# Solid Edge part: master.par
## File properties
Author: Vicky Raina
Template: Normal.par
Last saved by: Robert a Rhodes jr
Revision: 1
Application: Solid Edge
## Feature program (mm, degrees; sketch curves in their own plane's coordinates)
body "unnamed Body 1"
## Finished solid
Body 1: solid body, 75 faces, 214 edges, 140 vertices.
  Faces by surface: cylinder 56, plane 19
  Edges by curve: circle 102, line 100, spline 12
Bounding box of the edges (mm): 7327.900 x 1778.000 x 2844.800, from (-1244.6, -355.6, -1422.4) to (6083.3, 1422.4, 1422.4).
Cylindrical faces by radius (mm): R152.4 x20, R304.8 x2, R330.2 x8, R444.5 x2, R635 x2, R660.4 x2, R800.1 x6, R1473.2 x4, R1828.8 x6, R1981.2 x4
Planar faces by outward normal: +y 5, +z 2, -x 1, -y 5, -z 2, oblique 4
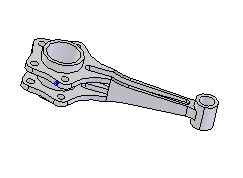
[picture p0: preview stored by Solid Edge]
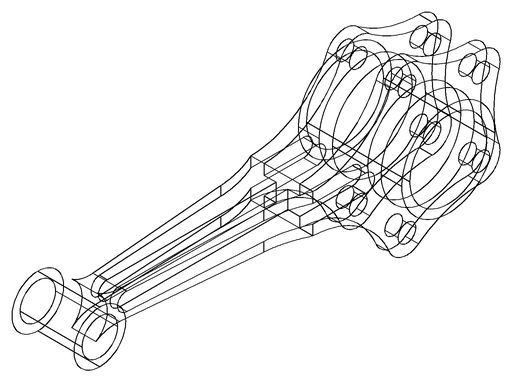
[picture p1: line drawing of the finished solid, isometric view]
